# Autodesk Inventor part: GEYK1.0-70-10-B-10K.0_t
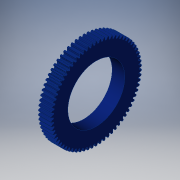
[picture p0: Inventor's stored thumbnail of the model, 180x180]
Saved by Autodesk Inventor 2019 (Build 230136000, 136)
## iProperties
Created: 2022-11
Part Number: GEYK1.0-70-10-B-10K.0_t
Material: Generic
Catalog Web Link: www.cadenas.de
Description: GEY_teeth-Plastic Bonded Spur Gears
Vendor: MISUMI
Document SubType Name: Modeling
Designer: psAdmin
Manufacturer: MISUMI
Mass: 22.3714 g
Surface Area: 101.789 cm^2
Volume: 22.3714 cm^3
Density: 1 g/cm^3
Appearance: PSOLRGB-87-140-238
Category: PARTsolutions
Company: MISUMI
Title: GEYK1.0-70-10-B-10K.0
Author: Cadenas PARTsolutions
Comments: Plastic Bonded Spur Gears
PSOL_IDENT_0: {$CADENAS_DATA/23d-libs/misumi/metric/54_spur_gears/gey_teeth.prj},214 {VTYP=3D},{NB=GEYK1.0-70-10-B
PSOL_IDENT_1: -10K.0_t},{LINA=GEYK1.0-70-10-B-10K.0},{NN=GEY_teeth},{DATE=07.06.2021 01:25:59},{GEOMDATE=22.08.201
PSOL_IDENT_2: 6 07:24:18},{VERSION=},{LINEID=10},{WBVAR=SHS,NT,PS,ALT1,ALT2,BS},{WBNUMERIC=NT,BS}  {NB=GEYK1.0-70-
PSOL_IDENT_3: 10-B-10K.0_t},{LINA=GEYK1.0-70-10-B-10K.0},{KT=DUMMY},{PN=GEYK1.0-70-10-B-10K.0},{SHS=K},{SHSPN=K},{
PSOL_IDENT_4: GEAKBH=0},{MAT=MC Nylon},{MATC=S25C},{AC=Set Screw},{MOD=1.0},{NT=70},{NTA=30,32,34,35,36,38,40,42,4
PSOL_IDENT_5: 5,48,50,52,56,60,70,75},{B=10},{TS=B},{TSA='B','B'},{PS=10K},{PSA= '10N','10N','10K','10K','11N','11
PSOL_IDENT_6: N','12N','12N','13N','13N','14N','14N','15N','15N','16N','16N','17N','17N','18N','18N','19N','19N','
PSOL_IDENT_7: 20N','20N','21N','21N','22N','22N','23N','23N','24N','24N'},{PS1= '10','10','11','11','12','12','13'
PSOL_IDENT_8: ,'13','14','14','15','15','16','16','17','17','18','18','19','19','20','20','21','21','22','22','23'
PSOL_IDENT_9: ,'23','24','24','25','25','26','26','27','27','28','28'},{PS2= '10N','10N','10K','10K','11N','11N','
PSOL_IDENT_10: 12N','12N','13N','13N','14N','14N','15N','15N','16N','16N','17N','17N','18N','18N','19N','19N','20N'
PSOL_IDENT_11: ,'20N','21N','21N','22N','22N','23N','23N','24N','24N'},{P=10.00},{DD=70.0},{D=72.0},{G=67.5},{H=40}
PSOL_IDENT_12: ,{E=45},{L=20},{LL1=10},{LL2=5.000},{M=M4},{M2=4},{ACSS=M4x3},{TT=0},{BB=4},{ALT1=},{ALTA='','w/o Se
PSOL_IDENT_13: t Screw', '-KC90', 'with KC90 (Set Screw)', '-KC120', 'with KC120 (Set Screw)'},{SCREWL=3},{PLANE=20
PSOL_IDENT_14: },{PLANE1=20},{ALT2=},{ALT2A='','w/o Boss Cut','-BS','with BS (Boss Cut)'},{BS=0.0},{BSA=0},{BSMIN=7
PSOL_IDENT_15: .0},{BSMAX=9.5},{MOD3D=1},{D1=1.285714},{D2=2.571429},{D3=20},{D4=0.1},{D5=11.666667},{D6=10.769231}
PSOL_IDENT_16: ,{D7=0.85},{D8=0.5},{D9=0.82917},{S1=15},{S2=0.5}
NB: GEYK1.0-70-10-B-10K.0_t
NN: GEY_teeth
NT: 70
NBSYN: $PN._t
LINA: GEYK1.0-70-10-B-10K.0
CATALOG: Misumi
SHS: Key Groove Hole+Tap
MAT: MC Nylon
MATC: S25C
MOD: 1.0
B: 10
PS: 10K
L: 20
LL1: 10
ALT1: w/o Set Screw
ALT2: w/o Boss Cut
BS: 0
SUPPLIER: MISUMI
ARTICLENO: GEYK1.0-70-10-B-10K.0_t
BOMINFO: GEYK1.0-70-10-B-10K.0
CREATOR: CADENAS GmbH
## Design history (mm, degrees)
sketch "_____2"
  geometry: L1 (0, 0)-(-10, 0); L2 (-10, 22.5)-(0, 22.5); L3 (0, 22.5)-(0, 35.5); L4 (0, 35.5)-(-0.67, 38); L5 (-0.67, 38)-(-9.33, 38); L6 (-9.33, 38)-(-10, 35.5); L7 (-10, 35.5)-(-10, 22.5)
  constraints: 14 end point
revolve "Revolution1" sketch "_____2" stored, may be unused: angle "d0" = 360 deg
sketch "Sketch_2"
  geometry: C1 r 144 at (0, 0); A1 r 0.1 centre (1.285, 35.877) between (1.288, 35.977) and (1.195, 35.921); A2 r 11.667 centre (11.656, 30.756) between (1.195, 35.921) and (0.785, 34.991); A3 r 0.829 centre (1.558, 34.69) between (0.785, 34.991) and (0.75, 34.876); A4 r 10.769 centre (-9.746, 37.286) between (0.542, 34.102) and (0.75, 34.876); A5 r 0.5 centre (0.064, 34.25) between (0.063, 33.75) and (0.542, 34.102); A6 r 33.75 centre (0, 0) between (0.063, 33.75) and (-0.063, 33.75); A7 r 0.5 centre (-0.064, 34.25) between (-0.542, 34.102) and (-0.063, 33.75); A8 r 10.769 centre (9.746, 37.286) between (-0.75, 34.876) and (-0.542, 34.102); A9 r 0.829 centre (-1.558, 34.69) between (-0.75, 34.876) and (-0.785, 34.991); A10 r 11.667 centre (-11.656, 30.756) between (-0.785, 34.991) and (-1.195, 35.921); A11 r 0.1 centre (-1.285, 35.877) between (-1.195, 35.921) and (-1.288, 35.977); A12 r 36 centre (0, 0) between (-1.288, 35.977) and (-1.942, 35.948); A13 r 0.1 centre (-1.936, 35.848) between (-1.942, 35.948) and (-2.03, 35.884); A14 r 11.667 centre (8.852, 31.677) between (-2.03, 35.884) and (-2.354, 34.921); A15 r 0.829 centre (-1.558, 34.69) between (-2.354, 34.921) and (-2.379, 34.802); A16 r 10.769 centre (-13.049, 36.262) between (-2.517, 34.013) and (-2.379, 34.802); A17 r 0.5 centre (-3.006, 34.118) between (-2.963, 33.62) and (-2.517, 34.013); A18 r 33.75 centre (0, 0) between (-2.963, 33.62) and (-3.088, 33.608); A19 r 0.5 centre (-3.134, 34.106) between (-3.596, 33.916) and (-3.088, 33.608); A20 r 10.769 centre (6.365, 38.009) between (-3.873, 34.668) and (-3.596, 33.916); A21 r 0.829 centre (-4.661, 34.411) between (-3.873, 34.668) and (-3.919, 34.78); A22 r 11.667 centre (-14.366, 29.587) between (-3.919, 34.78) and (-4.41, 35.67); A23 r 0.1 centre (-4.496, 35.617) between (-4.41, 35.67) and (-4.508, 35.717); A24 r 36 centre (0, 0) between (-4.508, 35.717) and (-5.156, 35.629); A25 r 0.1 centre (-5.142, 35.53) between (-5.156, 35.629) and (-5.238, 35.557); A26 r 11.667 centre (5.977, 32.343) between (-5.238, 35.557) and (-5.475, 34.569); A27 r 0.829 centre (-4.661, 34.411) between (-5.475, 34.569) and (-5.49, 34.449); A28 r 10.769 centre (-16.247, 34.946) between (-5.556, 33.651) and (-5.49, 34.449); A29 r 0.5 centre (-6.053, 33.711) between (-5.964, 33.219) and (-5.556, 33.651); A30 r 33.75 centre (0, 0) between (-5.964, 33.219) and (-6.088, 33.196); A31 r 0.5 centre (-6.178, 33.688) between (-6.622, 33.457) and (-6.088, 33.196); A32 r 10.769 centre (2.932, 38.427) between (-6.965, 34.181) and (-6.622, 33.457); A33 r 0.829 centre (-7.727, 33.855) between (-6.965, 34.181) and (-7.021, 34.289); A34 r 11.667 centre (-16.96, 28.18) between (-7.021, 34.289) and (-7.59, 35.131); A35 r 0.1 centre (-7.67, 35.071) between (-7.59, 35.131) and (-7.692, 35.169); A36 r 36 centre (0, 0) between (-7.692, 35.169) and (-8.329, 35.023); A37 r 0.1 centre (-8.306, 34.926) between (-8.329, 35.023) and (-8.404, 34.945); A38 r 11.667 centre (3.054, 32.749) between (-8.404, 34.945) and (-8.552, 33.939); A39 r 0.829 centre (-7.727, 33.855) between (-8.552, 33.939) and (-8.555, 33.818); A40 r 10.769 centre (-19.314, 33.349) between (-8.55, 33.017) and (-8.555, 33.818); A41 r 0.5 centre (-9.05, 33.033) between (-8.918, 32.55) and (-8.55, 33.017); A42 r 33.75 centre (0, 0) between (-8.918, 32.55) and (-9.039, 32.517); A43 r 0.5 centre (-9.173, 32.999) between (-9.594, 32.729) and (-9.039, 32.517); A44 r 10.769 centre (-0.524, 38.535) between (-10.001, 33.419) and (-9.594, 32.729); A45 r 0.829 centre (-10.731, 33.026) between (-10.001, 33.419) and (-10.066, 33.521); A46 r 11.667 centre (-19.418, 26.547) between (-10.066, 33.521) and (-10.709, 34.309); A47 r 0.1 centre (-10.783, 34.242) between (-10.709, 34.309) and (-10.813, 34.338); A48 r 36 centre (0, 0) between (-10.813, 34.338) and (-11.435, 34.136); A49 r 0.1 centre (-11.403, 34.041) between (-11.435, 34.136) and (-11.503, 34.051); A50 r 11.667 centre (0.106, 32.89) between (-11.503, 34.051) and (-11.56, 33.036); A51 r 0.829 centre (-10.731, 33.026) between (-11.56, 33.036) and (-11.552, 32.915); A52 r 10.769 centre (-22.226, 31.484) between (-11.476, 32.118) and (-11.552, 32.915); A53 r 0.5 centre (-11.975, 32.088) between (-11.8, 31.62) and (-11.476, 32.118); A54 r 33.75 centre (0, 0) between (-11.8, 31.62) and (-11.918, 31.576); A55 r 0.5 centre (-12.094, 32.044) between (-12.49, 31.737) and (-11.918, 31.576); A56 r 10.769 centre (-3.977, 38.333) between (-12.956, 32.388) and (-12.49, 31.737); A57 r 0.829 centre (-13.648, 31.931) between (-12.956, 32.388) and (-13.03, 32.484); A58 r 11.667 centre (-21.72, 24.699) between (-13.03, 32.484) and (-13.741, 33.211); A59 r 0.1 centre (-13.809, 33.138) between (-13.741, 33.211) and (-13.848, 33.23); A60 r 36 centre (0, 0) between (-13.848, 33.23) and (-14.449, 32.973); A61 r 0.1 centre (-14.409, 32.882) between (-14.449, 32.973) and (-14.509, 32.883); A62 r 11.667 centre (-2.843, 32.768) between (-14.509, 32.883) and (-14.475, 31.867); A63 r 0.829 centre (-13.648, 31.931) between (-14.475, 31.867) and (-14.456, 31.747); A64 r 10.769 centre (-24.959, 29.365) between (-14.308, 30.96) and (-14.456, 31.747)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; 1 further point
  constraints: 1680 point on circle, 841 centre point
extrude "Extrusion1" cut sketch "Sketch_2" distance "d1" = 10; taper "d2" = 0 deg
node "teeth_to_body_XY"
node "teeth_to_body_YZ"
node "teeth_to_body_ZX"
node "teeth_to_body_X"
node "teeth_to_body_Y"
node "teeth_to_body_Z"
node "teeth_to_body_Center"
body "Solid1"
other parameters: "d3" = 0
